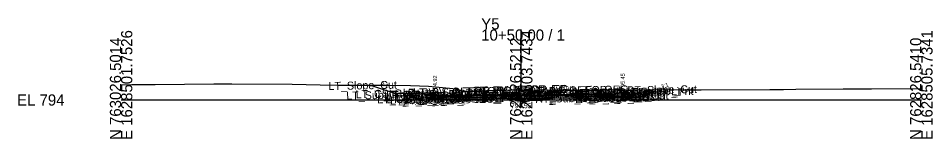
# Model space of a CAD drawing. Extents: x -26 to 203, y -10 to 6017.
# Drawn here: x -25.7 to 202.8, y 990.3 to 1020.5 of the extents above; entities that cross this region are included whole.
import ezdxf

# ---------------------------------------------------------------- set-up
doc = ezdxf.new("R2010")
doc.units = 0
for name, color, linetype in [('Default', 7, 'Continuous'), ('Exist CMT Pavement', 7, 'Continuous'), ('Exist Cross Section Cell', 7, 'Continuous'), ('Exist XS Center Line Elevation Label', 7, 'Continuous'), ('Exist XS Ground Line', 7, 'Continuous'), ('Prop CMT Conc Surface', 7, 'Continuous'), ('Prop CMT Concrete Structures', 7, 'Continuous'), ('Prop CMT Pvmt Course 1', 7, 'Continuous'), ('Prop CMT Pvmt Course 1 CG', 7, 'Continuous'), ('Prop CMT Pvmt Course 2', 7, 'Continuous'), ('Prop CMT Pvmt Course 2 Wedge', 7, 'Continuous'), ('Prop CMT Pvmt Course 3', 7, 'Continuous'), ('Prop CMT Pvmt Course 3 Wedge', 7, 'Continuous'), ('Prop CMT Pvmt Surface', 7, 'Continuous'), ('Prop CMT Pvmt Wedge Surface 1', 7, 'Continuous'), ('Prop CMT Pvmt Wedge Surface 2', 7, 'Continuous'), ('Prop CMT Pvmt Wedge Surface 3', 7, 'Continuous'), ('Prop CMT Slope Grass', 7, 'Continuous'), ('Prop CMT Subgrade Earthwork', 7, 'Continuous'), ('Prop XS Hydro Elevations', 7, 'Continuous'), ('Prop XS SE Text', 7, 'Continuous'), ('Prop XS Side Slope Text', 7, 'Continuous'), ('Scratch_Level_0', 7, 'Continuous')]:
    doc.layers.add(name, color=color, linetype=linetype)

msp = doc.modelspace()

# ---------------------------------------------------------------- linework, layer by layer
at = {"layer": 'Exist CMT Pavement'}
for points in [[(100, 1002.55), (85.48, 1002.12)], [(100, 1002.55), (114.33, 1002.42)]]:
    msp.add_lwpolyline(points, dxfattribs=at)
at = {"layer": 'Exist Cross Section Cell'}
for p, q in [((100, 1000), (100, 1017.65)), ((0, 1000), (100, 1000)), ((100, 1000), (200, 1000))]:
    msp.add_line(p, q, dxfattribs=at)
at = {"layer": 'Exist XS Ground Line'}
msp.add_lwpolyline([(0, 1003.81), (2.71, 1003.84), (8.48, 1003.88), (23.15, 1004.03), (27.65, 1004.03), (42.79, 1003.93), (49.76, 1003.81), (54.14, 1003.68), (63.58, 1003.7), (66.83, 1003.74), (72.33, 1003.6), (76.83, 1003.5), (83.81, 1002.77), (85.48, 1002.12), (91.17, 1002.32), (98.54, 1002.57), (100, 1002.55), (111.45, 1002.45), (114.33, 1002.42), (115.38, 1002.46), (124.73, 1002.66), (140.67, 1002.58), (144.99, 1002.55), (162.14, 1002.63), (165.53, 1002.66), (168.65, 1002.72), (180.45, 1002.78), (187.58, 1002.79), (200, 1002.85)], dxfattribs=at)
at = {"layer": 'Prop CMT Conc Surface'}
for points in [[(78.45, 1000.92), (78.45, 1001.42), (77.95, 1001.42)], [(80.45, 1001.03), (78.45, 1000.92)], [(123.39, 1001.51), (125.39, 1001.45)], [(125.39, 1001.45), (125.39, 1001.95), (125.89, 1001.95)]]:
    msp.add_lwpolyline(points, dxfattribs=at)
at = {"layer": 'Prop CMT Concrete Structures'}
for points in [[(80.45, 1001.03), (78.45, 1000.92), (78.45, 1001.42), (77.95, 1001.42)], [(77.95, 1001.42), (77.95, 1000.41), (80.45, 1000.44)], [(80.45, 1000.44), (80.45, 1001.03)], [(123.39, 1001.51), (125.39, 1001.45), (125.39, 1001.95), (125.89, 1001.95)], [(125.89, 1001.95), (125.89, 1000.95), (123.39, 1000.92)], [(123.39, 1000.92), (123.39, 1001.51)]]:
    msp.add_lwpolyline(points, dxfattribs=at)
at = {"layer": 'Prop CMT Pvmt Course 1'}
for points in [[(100, 1001.27), (80.45, 1001.03)], [(80.45, 1001.03), (80.45, 1000.78)], [(100, 1001.27), (123.39, 1001.51)], [(100, 1001.02), (100, 1001.27)], [(100, 1001.02), (100, 1001.27)], [(100, 1001.15), (100, 1001.02), (100, 1001.02)], [(100, 1001.15), (100, 1001.02), (100, 1001.02)], [(123.39, 1001.51), (123.39, 1001.26)]]:
    msp.add_lwpolyline(points, dxfattribs=at)
at = {"layer": 'Prop CMT Pvmt Course 1 CG'}
for points in [[(80.45, 1000.44), (77.45, 1000.41), (77.11, 1000.07)], [(77.11, 1000.07), (80.45, 1000.11)], [(80.45, 1000.11), (80.45, 1000.44)], [(123.39, 1000.92), (126.39, 1000.95), (126.72, 1000.62)], [(123.39, 1000.59), (123.39, 1000.92)], [(126.72, 1000.62), (123.39, 1000.59)]]:
    msp.add_lwpolyline(points, dxfattribs=at)
at = {"layer": 'Prop CMT Pvmt Course 2'}
for points in [[(123.39, 1001.26), (123.39, 1000.92)], [(80.45, 1000.78), (80.45, 1000.44)]]:
    msp.add_lwpolyline(points, dxfattribs=at)
at = {"layer": 'Prop CMT Pvmt Course 2 Wedge'}
for points in [[(100, 1001.02), (80.45, 1000.78)], [(100, 1001.02), (123.39, 1001.26)]]:
    msp.add_lwpolyline(points, dxfattribs=at)
at = {"layer": 'Prop CMT Pvmt Course 3'}
for points in [[(80.45, 1000.44), (80.45, 1000.11)], [(80.45, 1000.11), (85.48, 1000.17)], [(123.39, 1000.59), (114.33, 1000.5)], [(123.39, 1000.92), (123.39, 1000.59)]]:
    msp.add_lwpolyline(points, dxfattribs=at)
at = {"layer": 'Prop CMT Pvmt Course 3 Wedge'}
for points in [[(100, 1000.69), (80.45, 1000.44)], [(100, 1000.69), (123.39, 1000.92)]]:
    msp.add_lwpolyline(points, dxfattribs=at)
at = {"layer": 'Prop CMT Pvmt Surface'}
for points in [[(100, 1001.27), (80.45, 1001.03)], [(100, 1001.27), (123.39, 1001.51)]]:
    msp.add_lwpolyline(points, dxfattribs=at)
at = {"layer": 'Prop CMT Pvmt Wedge Surface 1'}
for points in [[(80.45, 1000.78), (80.45, 1001.03)], [(123.39, 1001.26), (123.39, 1001.51)]]:
    msp.add_lwpolyline(points, dxfattribs=at)
at = {"layer": 'Prop CMT Pvmt Wedge Surface 2'}
for points in [[(80.45, 1000.78), (80.45, 1001.03)], [(123.39, 1001.26), (123.39, 1001.51)]]:
    msp.add_lwpolyline(points, dxfattribs=at)
at = {"layer": 'Prop CMT Pvmt Wedge Surface 3'}
for points in [[(80.45, 1000.44), (80.45, 1001.03)], [(123.39, 1000.92), (123.39, 1001.51)]]:
    msp.add_lwpolyline(points, dxfattribs=at)
at = {"layer": 'Prop CMT Slope Grass'}
for points in [[(77.95, 1001.42), (68.45, 1001.61), (62.19, 1003.7)], [(125.89, 1001.95), (135.39, 1002.14), (136.78, 1002.6)]]:
    msp.add_lwpolyline(points, dxfattribs=at)
at = {"layer": 'Prop CMT Subgrade Earthwork'}
for points in [[(80.45, 1000.11), (77.11, 1000.07), (75.71, 1001.47)], [(123.39, 1000.59), (126.72, 1000.62), (128.09, 1001.99)], [(100, 1000.36), (80.45, 1000.11)], [(100, 1000.36), (123.39, 1000.59)]]:
    msp.add_lwpolyline(points, dxfattribs=at)

# ---------------------------------------------------------------- texts
at = {"layer": 'Default'}
msp.add_text('-', height=0.0001, dxfattribs=at).set_placement((0, 1000))
at = {"layer": 'Exist Cross Section Cell'}
for s, p in [('Y5', (90, 1017.65)), ('10+50.00 / 1', (90, 1014.85)), ('EL 794', (-26, 998.6))]:
    msp.add_text(s, height=2.8, dxfattribs=at).set_placement(p)
for s, p in [('E 1628501.7526', (2.8, 990)), ('E 1628503.7434', (102.8, 990)), ('E 1628505.7341', (202.8, 990)), ('N 763026.5014', (0, 990)), ('N 762926.5212', (100, 990)), ('N 762826.5410', (200, 990))]:
    msp.add_text(s, height=2.8, rotation=90, dxfattribs=at).set_placement(p)
at = {"layer": 'Exist XS Center Line Elevation Label'}
msp.add_text('796.55', height=1.2, dxfattribs=at).set_placement((97.46, 997.95))
at = {"layer": 'Prop XS Hydro Elevations'}
for s, p in [('794.92', (78.95, 1001.92)), ('795.45', (125.89, 1002.45))]:
    msp.add_text(s, height=1, rotation=90, dxfattribs=at).set_placement(p)
at = {"layer": 'Prop XS SE Text'}
for s, rotation, p in [('0.010', 0.5729, (110.06, 1002.37)), ('0.013', 0.7162, (88.6, 1002.13))]:
    msp.add_text(s, height=1, rotation=rotation, dxfattribs=at).set_placement(p)
at = {"layer": 'Prop XS Side Slope Text'}
for rotation, p in [(341.5668, (64.8, 1003.62)), (18.4332, (135.1, 1002.83))]:
    msp.add_text('3:1', height=1, rotation=rotation, dxfattribs=at).set_placement(p)
at = {"layer": 'Scratch_Level_0'}
for s, p in [('LT_Slope_Cut', (51.85, 1002.49)), ('LT_PV_Sub_Tie_Out', (70.46, 1000.82)), ('LT_PV_OEEOP_EG', (73.05, 1000.88)), ('RT_PV_IEEOP_EG', (88.16, 1001.32)), ('LT_PV_IEEOP_EG', (88.21, 1001.32)), ('RT_PV_Sub_Tie_Out', (99.23, 1001.12)), ('RT_PV_OEEOP_EG', (101.84, 1001.17)), ('RT_Slope_Cut', (126.4, 1001.39)), ('LT_Sub_Trench_Out_DLT', (56.3, 1000.08)), ('LT_CSLP_Pnt', (58.64, 1000.42)), ('LT_CG1_Shelf_Out', (64.02, 999.14)), ('LT_CG_Top_Face', (65.73, 1000.17)), ('LT_CG_Top_BOC', (66.25, 1000.19)), ('LT_CG_Bot_BOC', (66.29, 999.18)), ('LT_CG_Top_Gut', (66.71, 999.69)), ('LT_Sub_OEOP', (67.24, 998.87)), ('LT_CG_Bot_IE', (70.38, 999.24)), ('LT_Sub_OEOT', (70.55, 998.91)), ('LT_PV2_OEOT', (70.64, 999.58)), ('LT_PV3_OEOT', (70.64, 999.25)), ('LT_PV1_OEOT', (71.21, 999.84)), ('LT_Sub_OEEOP', (74.71, 998.96)), ('LT_PV2_OEEOP', (74.81, 999.63)), ('LT_PV3_OEEOP', (74.81, 999.29)), ('LT_PV1_OEEOP', (75.38, 999.76)), ('RT_PV2_IEEOP', (89.93, 999.82)), ('RT_PV3_IEEOP', (89.93, 999.49)), ('LT_PV2_IEEOP', (89.97, 999.82)), ('LT_PV3_IEEOP', (89.97, 999.49)), ('RT_PV1_IEEOP', (90.49, 999.96)), ('LT_PV1_IEEOP', (90.54, 999.96)), ('PV2_PGL', (93.93, 999.9)), ('PV1_PGL', (94.49, 1000.16)), ('RT_Sub_OEEOP', (103.51, 999.28)), ('RT_PV2_OEEOP', (103.61, 999.95)), ('RT_PV3_OEEOP', (103.61, 999.62)), ('RT_PV1_OEEOP', (104.17, 1000.09)), ('RT_Sub_Trench_Out_DLT', (108.63, 1000.6)), ('RT_CG_Top_Face', (112.63, 1000.69)), ('RT_CG1_Shelf_Out', (112.92, 999.68)), ('RT_CG_Bot_IE', (113.28, 999.72)), ('RT_Sub_OEOT', (113.45, 999.39)), ('RT_PV2_OEOT', (113.54, 1000.06)), ('RT_PV3_OEOT', (113.54, 999.73)), ('RT_CG_Top_Gut', (113.6, 1000.21)), ('RT_PV1_OEOT', (114.11, 1000.32)), ('RT_CG_Top_BOC', (114.15, 1000.71)), ('RT_CG_Bot_BOC', (114.18, 999.71)), ('RT_Sub_OEOP', (116.81, 999.42)), ('RT_CSLP_Pnt', (125.54, 1000.94))]:
    msp.add_text(s, height=2, rotation=1.1458, dxfattribs=at).set_placement(p)

doc.saveas('drawing.dxf')
